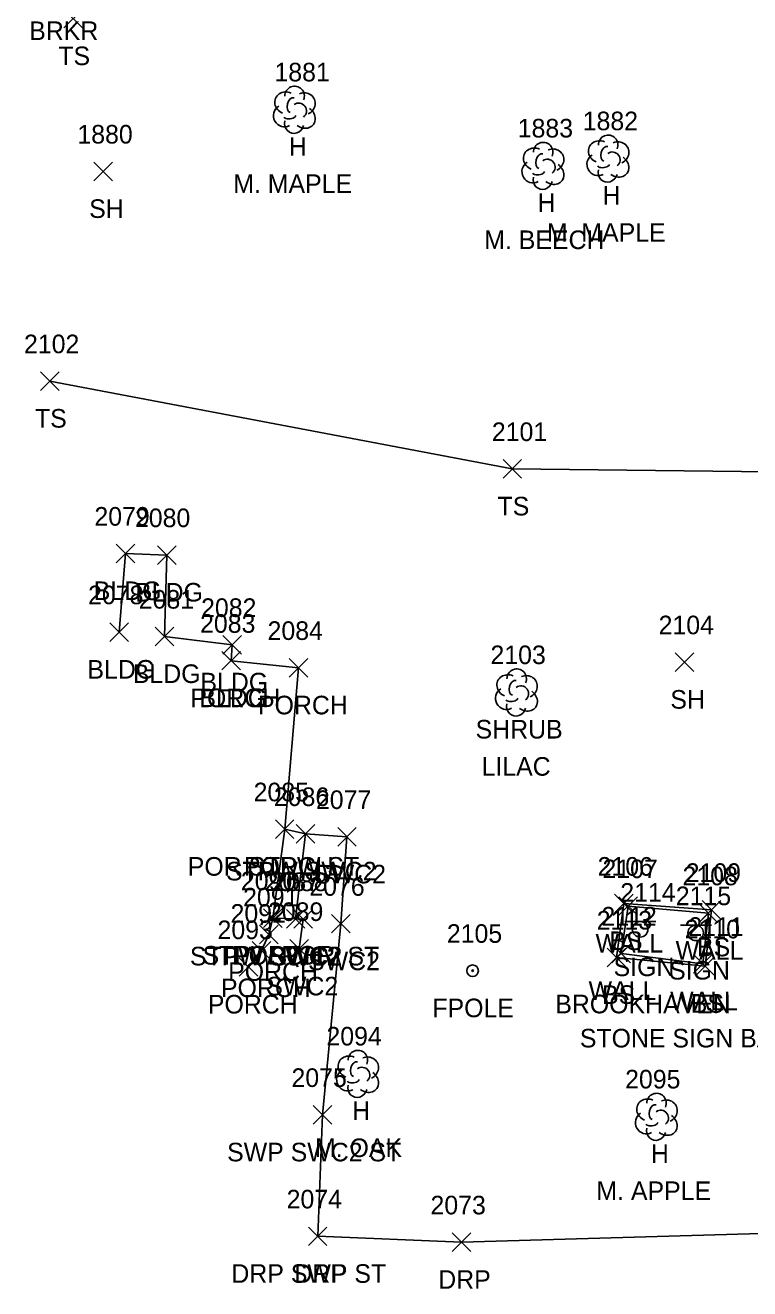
# Model space of a CAD drawing. Extents: x 1651305 to 1654558, y 539481 to 548441.
# Drawn here: x 1654257.2 to 1654335.1, y 544302 to 544437.8 of the extents above; entities that cross this region are included whole.
import ezdxf

# ---------------------------------------------------------------- set-up
doc = ezdxf.new("R2010")
doc.units = 0
for name, color, linetype in [('L_A', 7, 'Continuous'), ('L_C', 7, 'Continuous'), ('L_I', 7, 'Continuous'), ('L_TIC', 7, 'Continuous'), ('LBC', 7, 'Continuous'), ('LBF', 7, 'Continuous'), ('LELB', 7, 'Continuous'), ('LFP', 7, 'Continuous'), ('LSH', 7, 'Continuous'), ('LTD', 7, 'Continuous'), ('LW', 7, 'Continuous'), ('R_A', 7, 'Continuous'), ('R_I', 7, 'Continuous'), ('R_TIC', 7, 'Continuous'), ('RDP', 7, 'Continuous'), ('RSW', 7, 'Continuous'), ('S_A', 7, 'Continuous'), ('S_C', 7, 'Continuous'), ('S_I', 7, 'Continuous'), ('SSGN', 7, 'Continuous')]:
    doc.layers.add(name, color=color, linetype=linetype)

msp = doc.modelspace()

# ---------------------------------------------------------------- linework, layer by layer
at = {"layer": 'L_TIC'}
for points in [[(1654261.37, 544437.56), (1654263.37, 544439.56)], [(1654263.37, 544437.56), (1654261.37, 544439.56)], [(1654264.61, 544421.13), (1654266.61, 544423.13)], [(1654266.61, 544421.13), (1654264.61, 544423.13)], [(1654258.86, 544398.58), (1654260.86, 544400.58)], [(1654260.86, 544398.58), (1654258.86, 544400.58)], [(1654308.6, 544389.14), (1654310.6, 544391.14)], [(1654310.6, 544389.14), (1654308.6, 544391.14)], [(1654267, 544380.04), (1654269, 544382.04)], [(1654269, 544380.04), (1654267, 544382.04)], [(1654271.45, 544379.88), (1654273.45, 544381.88)], [(1654273.45, 544379.88), (1654271.45, 544381.88)], [(1654266.32, 544371.59), (1654268.32, 544373.59)], [(1654268.32, 544371.59), (1654266.32, 544373.59)], [(1654271.2, 544371.12), (1654273.2, 544373.12)], [(1654273.2, 544371.12), (1654271.2, 544373.12)], [(1654278.47, 544370.22), (1654280.47, 544372.22)], [(1654280.47, 544370.22), (1654278.47, 544372.22)], [(1654278.36, 544368.52), (1654280.36, 544370.52)], [(1654280.36, 544368.52), (1654278.36, 544370.52)], [(1654278.36, 544368.52), (1654280.36, 544370.52)], [(1654280.36, 544368.52), (1654278.36, 544370.52)], [(1654327.1, 544368.36), (1654329.1, 544370.36)], [(1654329.1, 544368.36), (1654327.1, 544370.36)], [(1654285.62, 544367.75), (1654287.62, 544369.75)], [(1654287.62, 544367.75), (1654285.62, 544369.75)], [(1654284.12, 544350.4), (1654286.12, 544352.4)], [(1654286.12, 544350.4), (1654284.12, 544352.4)], [(1654284.12, 544350.4), (1654286.12, 544352.4)], [(1654286.12, 544350.4), (1654284.12, 544352.4)], [(1654286.35, 544349.89), (1654288.35, 544351.89)], [(1654288.35, 544349.89), (1654286.35, 544351.89)], [(1654320.6, 544342.4), (1654322.6, 544344.4)], [(1654322.6, 544342.4), (1654320.6, 544344.4)], [(1654320.6, 544342.4), (1654322.6, 544344.4)], [(1654322.6, 544342.4), (1654320.6, 544344.4)], [(1654282.84, 544340.84), (1654284.84, 544342.84)], [(1654284.84, 544340.84), (1654282.84, 544342.84)], [(1654282.84, 544340.84), (1654284.84, 544342.84)], [(1654284.84, 544340.84), (1654282.84, 544342.84)], [(1654321.06, 544342.14), (1654323.06, 544344.14)], [(1654323.06, 544342.14), (1654321.06, 544344.14)], [(1654321.06, 544342.14), (1654323.06, 544344.14)], [(1654323.06, 544342.14), (1654321.06, 544344.14)], [(1654329.68, 544341.37), (1654331.68, 544343.37)], [(1654331.68, 544341.37), (1654329.68, 544343.37)], [(1654330.02, 544341.73), (1654332.02, 544343.73)], [(1654332.02, 544341.73), (1654330.02, 544343.73)], [(1654285.3, 544340.75), (1654287.3, 544342.75)], [(1654287.3, 544340.75), (1654285.3, 544342.75)], [(1654282.42, 544339.09), (1654284.42, 544341.09)], [(1654284.42, 544339.09), (1654282.42, 544341.09)], [(1654281.64, 544337.34), (1654283.64, 544339.34)], [(1654283.64, 544337.34), (1654281.64, 544339.34)], [(1654320.31, 544337.04), (1654322.31, 544339.04)], [(1654322.31, 544337.04), (1654320.31, 544339.04)], [(1654320.31, 544337.04), (1654322.31, 544339.04)], [(1654322.31, 544337.04), (1654320.31, 544339.04)], [(1654280.23, 544335.58), (1654282.23, 544337.58)], [(1654282.23, 544335.58), (1654280.23, 544337.58)], [(1654319.81, 544336.61), (1654321.81, 544338.61)], [(1654321.81, 544336.61), (1654319.81, 544338.61)], [(1654319.81, 544336.61), (1654321.81, 544338.61)], [(1654321.81, 544336.61), (1654319.81, 544338.61)], [(1654329.08, 544335.93), (1654331.08, 544337.93)], [(1654331.08, 544335.93), (1654329.08, 544337.93)], [(1654329.35, 544335.66), (1654331.35, 544337.66)], [(1654331.35, 544335.66), (1654329.35, 544337.66)]]:
    msp.add_lwpolyline(points, dxfattribs=at)
at = {"layer": 'LBC'}
msp.add_lwpolyline([(1654267.32, 544372.59), (1654268, 544381.04), (1654272.45, 544380.88), (1654272.2, 544372.12), (1654279.47, 544371.22), (1654279.36, 544369.52)], dxfattribs=at)
at = {"layer": 'LBF'}
for points in [[(1654279.36, 544369.52), (1654286.62, 544368.75), (1654285.12, 544351.4), (1654283.84, 544341.84), (1654283.42, 544340.09), (1654282.64, 544338.34), (1654281.23, 544336.58)], [(1654285.12, 544351.4), (1654287.35, 544350.89), (1654286.3, 544341.75), (1654283.84, 544341.84)]]:
    msp.add_lwpolyline(points, dxfattribs=at)
at = {"layer": 'LELB'}
for points in [[(1654340.41, 544389.78), (1654309.6, 544390.14), (1654259.86, 544399.58)], [(1654321.6, 544343.4), (1654331.02, 544342.73), (1654330.35, 544336.66), (1654320.81, 544337.61)], [(1654321.6, 544343.4), (1654320.81, 544337.61)]]:
    msp.add_lwpolyline(points, dxfattribs=at)
at = {"layer": 'LFP'}
for radius in [0.625, 0.0833]:
    msp.add_circle((1654305.33, 544336.18), radius, dxfattribs=at)
at = {"layer": 'LSH'}
msp.add_line((1654310.02, 544366.15), (1654310.02, 544366.15), dxfattribs=at)
msp.add_line((1654310.02, 544366.15), (1654310.02, 544366.15), dxfattribs=at)
msp.add_arc((1654310.07, 544367.58), 1.05, 335.5272, 180.9563, dxfattribs=at)
for centre, major_axis, ratio, start_param, end_param in [((1654309.23, 544366.81), (1.21, -0.51), 0.895232, 1.570796, 4.712389), ((1654309.81, 544366.6), (-0.208, -0.792), 0.645439, 3.141593, 6.283185), ((1654311.06, 544366.73), (-1.14, -0.48), 0.949671, 1.570796, 4.712389), ((1654308.94, 544365.44), (0.58, -1.04), 0.959034, 3.141593, 6.283185), ((1654310.52, 544365.98), (-0.5, 0.667), 0.989748, 3.141593, 6.283185), ((1654311.02, 544365.31), (-1.09, 0.79), 0.841452, 1.570796, 4.712389), ((1654310.02, 544364.65), (0.26, 1.06), 0.942809, 1.570796, 4.712389), ((1654309.56, 544365.4), (-0.625, -0.083), 0.423636, 0, 3.141593)]:
    msp.add_ellipse(centre, major_axis=major_axis, ratio=ratio, start_param=start_param, end_param=end_param, dxfattribs=at)
at = {"layer": 'LTD'}
for p, q in [((1654286.14, 544428.81), (1654286.14, 544428.81)), ((1654286.14, 544428.81), (1654286.14, 544428.81)), ((1654319.86, 544423.56), (1654319.86, 544423.56)), ((1654319.86, 544423.56), (1654319.86, 544423.56)), ((1654312.87, 544422.78), (1654312.87, 544422.78)), ((1654312.87, 544422.78), (1654312.87, 544422.78)), ((1654292.94, 544325.14), (1654292.94, 544325.14)), ((1654292.94, 544325.14), (1654292.94, 544325.14)), ((1654325.06, 544320.52), (1654325.06, 544320.52)), ((1654325.06, 544320.52), (1654325.06, 544320.52))]:
    msp.add_line(p, q, dxfattribs=at)
for centre in [(1654286.19, 544430.25), (1654319.91, 544424.99), (1654312.92, 544424.21), (1654292.99, 544326.57), (1654325.11, 544321.95)]:
    msp.add_arc(centre, 1.05, 335.5272, 180.9563, dxfattribs=at)
for centre, major_axis, ratio, start_param, end_param in [((1654285.35, 544429.48), (1.21, -0.51), 0.895232, 1.570796, 4.712389), ((1654285.93, 544429.27), (-0.208, -0.792), 0.645439, 3.141593, 6.283185), ((1654287.18, 544429.4), (-1.14, -0.48), 0.949671, 1.570796, 4.712389), ((1654285.06, 544428.1), (0.58, -1.04), 0.959034, 3.141593, 6.283185), ((1654286.64, 544428.65), (-0.5, 0.667), 0.989748, 3.141593, 6.283185), ((1654287.14, 544427.98), (-1.09, 0.79), 0.841452, 1.570796, 4.712389), ((1654286.14, 544427.31), (0.26, 1.06), 0.942809, 1.570796, 4.712389), ((1654285.68, 544428.06), (-0.625, -0.083), 0.423636, 0, 3.141593), ((1654312.08, 544423.45), (1.21, -0.51), 0.895232, 1.570796, 4.712389), ((1654313.92, 544423.36), (-1.14, -0.48), 0.949671, 1.570796, 4.712389), ((1654319.07, 544424.23), (1.21, -0.51), 0.895232, 1.570796, 4.712389), ((1654319.66, 544424.02), (-0.208, -0.792), 0.645439, 3.141593, 6.283185), ((1654320.36, 544423.39), (-0.5, 0.667), 0.989748, 3.141593, 6.283185), ((1654320.91, 544424.14), (-1.14, -0.48), 0.949671, 1.570796, 4.712389), ((1654311.79, 544422.07), (0.58, -1.04), 0.959034, 3.141593, 6.283185), ((1654312.67, 544423.24), (-0.208, -0.792), 0.645439, 3.141593, 6.283185), ((1654313.37, 544422.61), (-0.5, 0.667), 0.989748, 3.141593, 6.283185), ((1654318.78, 544422.85), (0.58, -1.04), 0.959034, 3.141593, 6.283185), ((1654320.86, 544422.73), (-1.09, 0.79), 0.841452, 1.570796, 4.712389), ((1654312.42, 544422.03), (-0.625, -0.083), 0.423636, 0, 3.141593), ((1654313.87, 544421.95), (-1.09, 0.79), 0.841452, 1.570796, 4.712389), ((1654319.86, 544422.06), (0.26, 1.06), 0.942809, 1.570796, 4.712389), ((1654319.41, 544422.81), (-0.625, -0.083), 0.423636, 0, 3.141593), ((1654312.87, 544421.28), (0.26, 1.06), 0.942809, 1.570796, 4.712389), ((1654292.15, 544325.81), (1.21, -0.51), 0.895232, 1.570796, 4.712389), ((1654293.99, 544325.72), (-1.14, -0.48), 0.949671, 1.570796, 4.712389), ((1654291.86, 544324.43), (0.58, -1.04), 0.959034, 3.141593, 6.283185), ((1654292.74, 544325.6), (-0.208, -0.792), 0.645439, 3.141593, 6.283185), ((1654293.44, 544324.97), (-0.5, 0.667), 0.989748, 3.141593, 6.283185), ((1654293.94, 544324.31), (-1.09, 0.79), 0.841452, 1.570796, 4.712389), ((1654292.94, 544323.64), (0.26, 1.06), 0.942809, 1.570796, 4.712389), ((1654292.49, 544324.39), (-0.625, -0.083), 0.423636, 0, 3.141593), ((1654324.27, 544321.19), (1.21, -0.51), 0.895232, 1.570796, 4.712389), ((1654326.11, 544321.1), (-1.14, -0.48), 0.949671, 1.570796, 4.712389), ((1654324.86, 544320.98), (-0.208, -0.792), 0.645439, 3.141593, 6.283185), ((1654325.56, 544320.35), (-0.5, 0.667), 0.989748, 3.141593, 6.283185), ((1654323.98, 544319.81), (0.58, -1.04), 0.959034, 3.141593, 6.283185), ((1654324.61, 544319.77), (-0.625, -0.083), 0.423636, 0, 3.141593), ((1654326.06, 544319.69), (-1.09, 0.79), 0.841452, 1.570796, 4.712389), ((1654325.06, 544319.02), (0.26, 1.06), 0.942809, 1.570796, 4.712389)]:
    msp.add_ellipse(centre, major_axis=major_axis, ratio=ratio, start_param=start_param, end_param=end_param, dxfattribs=at)
at = {"layer": 'LW'}
for points in [[(1654322.06, 544343.14), (1654330.68, 544342.37), (1654330.08, 544336.93), (1654321.31, 544338.04)], [(1654322.06, 544343.14), (1654321.31, 544338.04)]]:
    msp.add_lwpolyline(points, dxfattribs=at)
at = {"layer": 'R_TIC'}
for points in [[(1654286.35, 544349.89), (1654288.35, 544351.89)], [(1654288.35, 544349.89), (1654286.35, 544351.89)], [(1654290.82, 544349.57), (1654292.82, 544351.57)], [(1654292.82, 544349.57), (1654290.82, 544351.57)], [(1654285.3, 544340.75), (1654287.3, 544342.75)], [(1654287.3, 544340.75), (1654285.3, 544342.75)], [(1654286.11, 544340.74), (1654288.11, 544342.74)], [(1654288.11, 544340.74), (1654286.11, 544342.74)], [(1654290.17, 544340.24), (1654292.17, 544342.24)], [(1654292.17, 544340.24), (1654290.17, 544342.24)], [(1654285.68, 544337.53), (1654287.68, 544339.53)], [(1654287.68, 544337.53), (1654285.68, 544339.53)], [(1654288.19, 544319.68), (1654290.19, 544321.68)], [(1654290.19, 544319.68), (1654288.19, 544321.68)], [(1654288.19, 544319.68), (1654290.19, 544321.68)], [(1654290.19, 544319.68), (1654288.19, 544321.68)], [(1654287.67, 544306.62), (1654289.67, 544308.62)], [(1654289.67, 544306.62), (1654287.67, 544308.62)], [(1654287.67, 544306.62), (1654289.67, 544308.62)], [(1654289.67, 544306.62), (1654287.67, 544308.62)], [(1654303.14, 544305.98), (1654305.14, 544307.98)], [(1654305.14, 544305.98), (1654303.14, 544307.98)]]:
    msp.add_lwpolyline(points, dxfattribs=at)
at = {"layer": 'RDP'}
msp.add_lwpolyline([(1654364.49, 544322.02), (1654357.62, 544315.77), (1654348.31, 544309.85), (1654342.52, 544308.1), (1654304.14, 544306.98), (1654288.67, 544307.62)], dxfattribs=at)
at = {"layer": 'RSW'}
for points in [[(1654289.19, 544320.68), (1654291.17, 544341.24), (1654291.82, 544350.57), (1654287.35, 544350.89)], [(1654286.3, 544341.75), (1654287.11, 544341.74), (1654286.68, 544338.53)], [(1654288.67, 544307.62), (1654289.19, 544320.68)]]:
    msp.add_lwpolyline(points, dxfattribs=at)
at = {"layer": 'SSGN'}
for p, q in [((1654321.71, 544341.46), (1654325.04, 544341.46)), ((1654323.35, 544340.63), (1654323.35, 544340.63)), ((1654327.67, 544341.08), (1654331.01, 544341.08)), ((1654329.32, 544340.25), (1654329.32, 544340.25))]:
    msp.add_line(p, q, dxfattribs=at)
for centre in [(1654323.35, 544340.63), (1654329.32, 544340.25)]:
    msp.add_circle(centre, 0.833, dxfattribs=at)

# ---------------------------------------------------------------- texts
at = {"layer": 'L_A'}
for s, p in [('BRKR', (1654257.65, 544436.26)), ('TS', (1654260.78, 544433.56)), ('H', (1654285.57, 544423.81)), ('H', (1654319.3, 544418.56)), ('SH', (1654264.1, 544417.13)), ('H', (1654312.31, 544417.78)), ('TS', (1654258.27, 544394.58)), ('TS', (1654308.01, 544385.14)), ('BLDG', (1654264.59, 544376.04)), ('BLDG', (1654269.04, 544375.88)), ('BLDG', (1654263.91, 544367.59)), ('BLDG', (1654268.79, 544367.12)), ('BLDG', (1654276.06, 544366.22)), ('PORCH', (1654274.98, 544364.52)), ('BLDG', (1654275.95, 544364.52)), ('SH', (1654326.59, 544364.36)), ('PORCH', (1654282.25, 544363.75)), ('SHRUB', (1654305.65, 544361.15)), ('POR STPW ST', (1654274.7, 544346.4)), ('PORCH', (1654280.74, 544346.4)), ('STPW SWC2', (1654278.81, 544345.89)), ('WALL', (1654318.55, 544338.14)), ('WALL', (1654318.55, 544338.14)), ('BS', (1654320.04, 544338.4)), ('BS', (1654320.04, 544338.4)), ('STPW SWC2 ST', (1654274.93, 544336.75)), ('STPW POR', (1654276.29, 544336.84)), ('PORCH', (1654279.46, 544336.84)), ('WALL', (1654327.16, 544337.37)), ('BS', (1654329.46, 544337.73)), ('PORCH', (1654279.04, 544335.09)), ('PORCH', (1654278.27, 544333.34)), ('WALL', (1654317.8, 544333.04)), ('WALL', (1654317.8, 544333.04)), ('PORCH', (1654276.86, 544331.58)), ('BS', (1654319.25, 544332.61)), ('BS', (1654319.25, 544332.61)), ('WALL', (1654326.57, 544331.93)), ('BS', (1654328.79, 544331.66)), ('FPOLE', (1654301, 544331.18)), ('H', (1654292.38, 544320.14)), ('H', (1654324.5, 544315.52))]:
    msp.add_text(s, height=2, dxfattribs=at).set_placement(p)
at = {"layer": 'L_C'}
for s, p in [('M. MAPLE', (1654279.59, 544419.81)), ('M. MAPLE', (1654313.31, 544414.56)), ('M. BEECH', (1654306.58, 544413.78)), ('LILAC', (1654306.29, 544357.15)), ('STONE SIGN BASE', (1654316.86, 544327.93)), ('M. OAK', (1654288.38, 544316.14)), ('M. APPLE', (1654318.64, 544311.52))]:
    msp.add_text(s, height=2, dxfattribs=at).set_placement(p)
at = {"layer": 'L_I'}
for s, p in [('1881', (1654284.02, 544431.81)), ('1882', (1654317.17, 544426.56)), ('1880', (1654262.83, 544425.13)), ('1883', (1654310.18, 544425.78)), ('2102', (1654257.09, 544402.58)), ('2101', (1654307.4, 544393.14)), ('2079', (1654264.66, 544384.04)), ('2080', (1654269.02, 544383.88)), ('2078', (1654263.98, 544375.59)), ('2081', (1654269.43, 544375.12)), ('2082', (1654276.13, 544374.22)), ('2083', (1654276.02, 544372.52)), ('2083', (1654276.02, 544372.52)), ('2104', (1654325.33, 544372.36)), ('2084', (1654283.28, 544371.75)), ('2103', (1654307.25, 544369.15)), ('2085', (1654281.78, 544354.4)), ('2085', (1654281.78, 544354.4)), ('2086', (1654283.96, 544353.89)), ('2106', (1654318.77, 544346.4)), ('2106', (1654318.77, 544346.4)), ('2107', (1654319.29, 544346.14)), ('2107', (1654319.29, 544346.14)), ('2108', (1654327.9, 544345.37)), ('2109', (1654328.24, 544345.73)), ('2090', (1654280.41, 544344.84)), ('2090', (1654280.41, 544344.84)), ('2087', (1654282.96, 544344.75)), ('2091', (1654280.65, 544343.09)), ('2092', (1654279.3, 544341.34)), ('2112', (1654319.18, 544341.04)), ('2112', (1654319.18, 544341.04)), ('2093', (1654277.9, 544339.58)), ('2113', (1654318.68, 544340.61)), ('2113', (1654318.68, 544340.61)), ('2110', (1654328.13, 544339.66)), ('2111', (1654328.53, 544339.93)), ('2105', (1654302.56, 544339.18)), ('2094', (1654289.61, 544328.14)), ('2095', (1654321.73, 544323.52))]:
    msp.add_text(s, height=2, dxfattribs=at).set_placement(p)
at = {"layer": 'R_A'}
for s, p in [('STPW SWC2', (1654278.81, 544345.89)), ('SWC2', (1654288.29, 544345.57)), ('STPW SWC2 ST', (1654274.93, 544336.75)), ('SWC2', (1654283.59, 544336.74)), ('SWC2', (1654287.64, 544336.24)), ('SWC2', (1654283.15, 544333.53)), ('SWP SWC2 ST', (1654278.93, 544315.68)), ('SWP SWC2 ST', (1654278.93, 544315.68)), ('DRP SWP ST', (1654279.39, 544302.62)), ('DRP', (1654286.16, 544302.62)), ('DRP', (1654301.63, 544301.98))]:
    msp.add_text(s, height=2, dxfattribs=at).set_placement(p)
at = {"layer": 'R_I'}
for s, p in [('2086', (1654283.96, 544353.89)), ('2077', (1654288.48, 544353.57)), ('2087', (1654282.96, 544344.75)), ('2088', (1654283.78, 544344.74)), ('2076', (1654287.77, 544344.24)), ('2089', (1654283.33, 544341.53)), ('2075', (1654285.85, 544323.68)), ('2075', (1654285.85, 544323.68)), ('2074', (1654285.33, 544310.62)), ('2074', (1654285.33, 544310.62)), ('2073', (1654300.8, 544309.98))]:
    msp.add_text(s, height=2, dxfattribs=at).set_placement(p)
at = {"layer": 'S_A'}
for p in [(1654320.49, 544335.6), (1654326.46, 544335.23)]:
    msp.add_text('SIGN', height=2, dxfattribs=at).set_placement(p)
at = {"layer": 'S_C'}
msp.add_text('BROOKHAVEN', height=2, dxfattribs=at).set_placement((1654314.22, 544331.6))
at = {"layer": 'S_I'}
for s, p in [('2114', (1654321.21, 544343.6)), ('2115', (1654327.18, 544343.23))]:
    msp.add_text(s, height=2, dxfattribs=at).set_placement(p)

doc.saveas('drawing.dxf')
